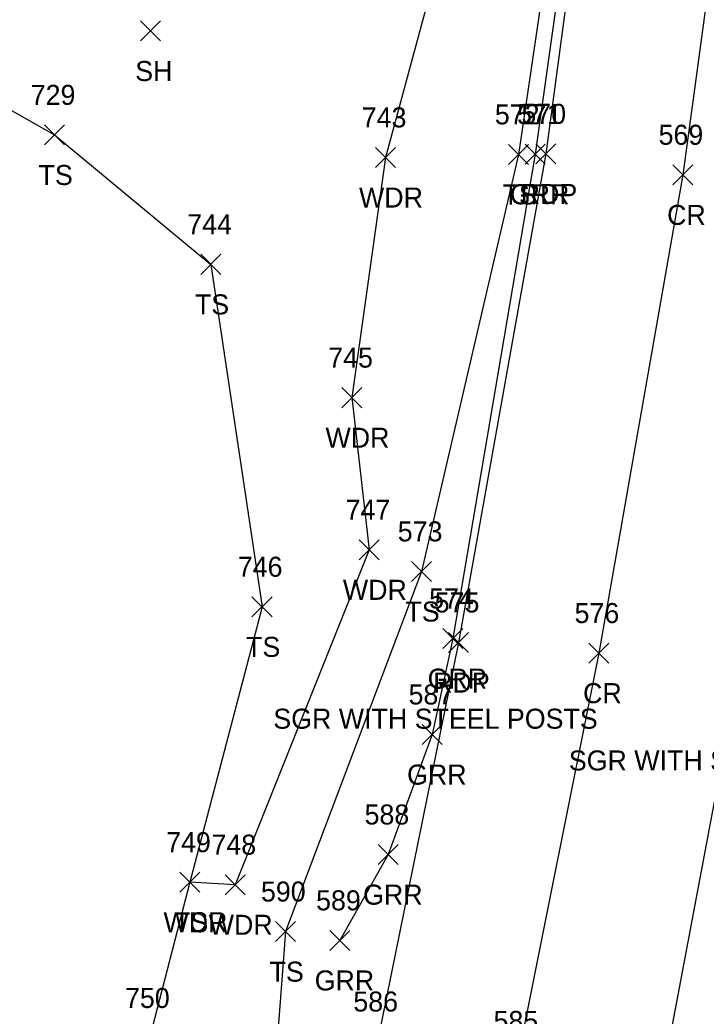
# Model space of a CAD drawing. Extents: x 1638705 to 1644019, y 630225 to 637423.
# Drawn here: x 1643815.9 to 1643884.4, y 636967.4 to 637066.8 of the extents above; entities that cross this region are included whole.
import ezdxf

# ---------------------------------------------------------------- set-up
doc = ezdxf.new("R2010")
doc.units = 0
for name, color, linetype in [('L_A', 7, 'Continuous'), ('L_I', 7, 'Continuous'), ('L_TIC', 7, 'Continuous'), ('LAWA', 7, 'Continuous'), ('LELB', 7, 'Continuous'), ('P_A', 7, 'Continuous'), ('P_I', 7, 'Continuous'), ('P_TIC', 7, 'Continuous'), ('PET', 7, 'Continuous'), ('PRC', 7, 'Continuous'), ('R_A', 7, 'Continuous'), ('R_C', 7, 'Continuous'), ('R_I', 7, 'Continuous'), ('R_TIC', 7, 'Continuous'), ('RGR', 7, 'Continuous')]:
    doc.layers.add(name, color=color, linetype=linetype)

msp = doc.modelspace()

# ---------------------------------------------------------------- linework, layer by layer
at = {"layer": 'L_TIC'}
for points in [[(1643827.902, 637064.719), (1643829.902, 637066.719)], [(1643829.902, 637064.719), (1643827.902, 637066.719)], [(1643818.326, 637054.337), (1643820.326, 637056.337)], [(1643820.326, 637054.337), (1643818.326, 637056.337)], [(1643851.377, 637052.09), (1643853.377, 637054.09)], [(1643853.377, 637052.09), (1643851.377, 637054.09)], [(1643864.671, 637052.392), (1643866.671, 637054.392)], [(1643866.671, 637052.392), (1643864.671, 637054.392)], [(1643833.946, 637041.419), (1643835.946, 637043.419)], [(1643835.946, 637041.419), (1643833.946, 637043.419)], [(1643848.031, 637028.108), (1643850.031, 637030.108)], [(1643850.031, 637028.108), (1643848.031, 637030.108)], [(1643849.768, 637012.923), (1643851.768, 637014.923)], [(1643851.768, 637012.923), (1643849.768, 637014.923)], [(1643854.971, 637010.755), (1643856.971, 637012.755)], [(1643856.971, 637010.755), (1643854.971, 637012.755)], [(1643839.052, 637007.228), (1643841.052, 637009.228)], [(1643841.052, 637007.228), (1643839.052, 637009.228)], [(1643831.852, 636979.729), (1643833.852, 636981.729)], [(1643833.852, 636979.729), (1643831.852, 636981.729)], [(1643831.852, 636979.729), (1643833.852, 636981.729)], [(1643833.852, 636979.729), (1643831.852, 636981.729)], [(1643836.369, 636979.48), (1643838.369, 636981.48)], [(1643838.369, 636979.48), (1643836.369, 636981.48)], [(1643841.397, 636974.8), (1643843.397, 636976.8)], [(1643843.397, 636974.8), (1643841.397, 636976.8)]]:
    msp.add_lwpolyline(points, dxfattribs=at)
at = {"layer": 'LAWA'}
msp.add_lwpolyline([(1643865.637, 637303.771), (1643862.824, 637270.267), (1643861.246, 637253.699), (1643870.987, 637241.898), (1643867.113, 637203.425), (1643864.21, 637161.34), (1643862.975, 637130.766), (1643854.224, 637098.036), (1643864.197, 637092.717), (1643858.236, 637074.74), (1643852.377, 637053.09), (1643849.031, 637029.108), (1643850.768, 637013.923), (1643837.369, 636980.48), (1643832.852, 636980.729), (1643828.819, 636965.176), (1643821.802, 636940.41), (1643821.758, 636915.632), (1643813.91, 636882.55), (1643810.67, 636866.311)], dxfattribs=at)
at = {"layer": 'LELB'}
for points in [[(1643881.311, 637303.513), (1643880.474, 637260.356), (1643877.748, 637219.48), (1643872.165, 637183.49), (1643871.11, 637167.528), (1643875.063, 637139.179), (1643871.644, 637093.847), (1643865.671, 637053.392), (1643855.971, 637011.755), (1643842.397, 636975.8), (1643838.297, 636921.937), (1643830.674, 636893.445), (1643822.68, 636863.816)], [(1643783.743, 637086.528), (1643786.224, 637071.711), (1643801.846, 637065.244), (1643819.326, 637055.337), (1643834.946, 637042.419), (1643840.052, 637008.228), (1643832.852, 636980.729)]]:
    msp.add_lwpolyline(points, dxfattribs=at)
at = {"layer": 'P_TIC'}
for points in [[(1643867.405, 637052.445), (1643869.405, 637054.445)], [(1643869.405, 637052.445), (1643867.405, 637054.445)], [(1643881.076, 637050.356), (1643883.076, 637052.356)], [(1643883.076, 637050.356), (1643881.076, 637052.356)], [(1643858.664, 637003.662), (1643860.664, 637005.662)], [(1643860.664, 637003.662), (1643858.664, 637005.662)], [(1643872.685, 637002.606), (1643874.685, 637004.606)], [(1643874.685, 637002.606), (1643872.685, 637004.606)]]:
    msp.add_lwpolyline(points, dxfattribs=at)
at = {"layer": 'PET'}
for points in [[(1643915.423, 637304.493), (1643914.603, 637262.423), (1643913.476, 637219.012), (1643911.31, 637181.13), (1643907.879, 637136.037), (1643902.195, 637091.185), (1643896.203, 637050.089), (1643887.538, 637001.119), (1643879.881, 636960.462), (1643869.1, 636915.332), (1643860.496, 636882.079), (1643852.885, 636856.282)], [(1643886.086, 637303.333), (1643885.326, 637260.945), (1643884.293, 637219.338), (1643882.651, 637181.954), (1643878.658, 637138.556), (1643873.794, 637093.657), (1643868.405, 637053.445), (1643859.664, 637004.662), (1643851.593, 636964.819), (1643841.079, 636921.123), (1643833.579, 636892.49), (1643824.771, 636863.462)]]:
    msp.add_lwpolyline(points, dxfattribs=at)
at = {"layer": 'PRC'}
msp.add_lwpolyline([(1643901.07, 637302.917), (1643900.038, 637261.191), (1643898.85, 637218.553), (1643896.698, 637181.823), (1643893.125, 637137.202), (1643887.511, 637091.293), (1643882.076, 637051.356), (1643873.685, 637003.606), (1643865.539, 636962.881), (1643854.81, 636918.076), (1643846.659, 636887.044), (1643838.687, 636859.965)], dxfattribs=at)
at = {"layer": 'R_TIC'}
for points in [[(1643866.32, 637052.415), (1643868.32, 637054.415)], [(1643868.32, 637052.415), (1643866.32, 637054.415)], [(1643858.105, 637004.056), (1643860.105, 637006.056)], [(1643860.105, 637004.056), (1643858.105, 637006.056)], [(1643856.051, 636994.477), (1643858.051, 636996.477)], [(1643858.051, 636994.477), (1643856.051, 636996.477)], [(1643851.659, 636982.492), (1643853.659, 636984.492)], [(1643853.659, 636982.492), (1643851.659, 636984.492)], [(1643846.825, 636973.922), (1643848.825, 636975.922)], [(1643848.825, 636973.922), (1643846.825, 636975.922)]]:
    msp.add_lwpolyline(points, dxfattribs=at)
at = {"layer": 'RGR'}
msp.add_lwpolyline([(1643876.35, 637173.625), (1643878.935, 637161.131), (1643878.763, 637152.024), (1643878.037, 637138.801), (1643872.949, 637093.475), (1643867.32, 637053.415), (1643859.105, 637005.056), (1643857.051, 636995.477), (1643852.659, 636983.492), (1643847.825, 636974.922)], dxfattribs=at)

# ---------------------------------------------------------------- texts
at = {"layer": 'L_A'}
for s, p in [('SH', (1643827.391, 637060.719)), ('TS', (1643817.736, 637050.337)), ('WDR', (1643849.739, 637048.09)), ('TS', (1643864.081, 637048.392)), ('TS', (1643833.355, 637037.419)), ('WDR', (1643846.393, 637024.108)), ('WDR', (1643848.13, 637008.923)), ('TS', (1643854.38, 637006.755)), ('TS', (1643838.462, 637003.228)), ('WDR', (1643830.214, 636975.729)), ('TS', (1643831.261, 636975.729)), ('WDR', (1643834.731, 636975.48)), ('TS', (1643840.806, 636970.8))]:
    msp.add_text(s, height=2, dxfattribs=at).set_placement(p)
at = {"layer": 'L_I'}
for s, p in [('729', (1643816.956, 637058.337)), ('743', (1643850.014, 637056.09)), ('572', (1643863.309, 637056.392)), ('744', (1643832.584, 637045.419)), ('745', (1643846.668, 637032.108)), ('747', (1643848.406, 637016.923)), ('573', (1643853.609, 637014.755)), ('746', (1643837.635, 637011.228)), ('749', (1643830.482, 636983.729)), ('749', (1643830.482, 636983.729)), ('748', (1643835.007, 636983.48)), ('590', (1643839.948, 636978.8)), ('750', (1643826.37, 636968.176)), ('750', (1643826.37, 636968.176))]:
    msp.add_text(s, height=2, dxfattribs=at).set_placement(p)
at = {"layer": 'P_A'}
for s, p in [('RDP', (1643865.893, 637048.445)), ('CR', (1643880.509, 637046.356)), ('RDP', (1643857.152, 636999.662)), ('CR', (1643872.118, 636998.606))]:
    msp.add_text(s, height=2, dxfattribs=at).set_placement(p)
at = {"layer": 'P_I'}
for s, p in [('570', (1643865.956, 637056.445)), ('569', (1643879.659, 637054.356)), ('575', (1643857.302, 637007.662)), ('576', (1643871.268, 637006.606)), ('586', (1643849.175, 636967.819)), ('585', (1643863.177, 636965.881))]:
    msp.add_text(s, height=2, dxfattribs=at).set_placement(p)
at = {"layer": 'R_A'}
for p in [(1643864.809, 637048.415), (1643856.594, 637000.056), (1643854.539, 636990.477), (1643850.147, 636978.492), (1643845.313, 636969.922)]:
    msp.add_text('GRR', height=2, dxfattribs=at).set_placement(p)
at = {"layer": 'R_C'}
for p in [(1643841.184, 636996.056), (1643870.694, 636991.886)]:
    msp.add_text('SGR WITH STEEL POSTS', height=2, dxfattribs=at).set_placement(p)
at = {"layer": 'R_I'}
for s, p in [('571', (1643865.525, 637056.415)), ('574', (1643856.743, 637008.056)), ('587', (1643854.689, 636998.477)), ('588', (1643850.296, 636986.492)), ('589', (1643845.455, 636977.922))]:
    msp.add_text(s, height=2, dxfattribs=at).set_placement(p)

doc.saveas('drawing.dxf')
